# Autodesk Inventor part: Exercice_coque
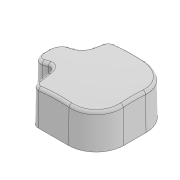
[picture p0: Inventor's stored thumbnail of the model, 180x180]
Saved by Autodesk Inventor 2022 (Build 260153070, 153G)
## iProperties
Created: 2019-12
Part Number: Exercice_coque
Material: Générique
Document SubType Name: Modeling
Designer: Fabian
Density: 1 g/cm^3
Appearance: Par défaut
Author: Fabian
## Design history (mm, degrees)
sketch "Esquisse1"
  geometry: L1 (0, 70)-(0, -66.117); L2 (90, 0)-(-70, 0); L3 (90, 14.325)-(90, 0); L4 (-70, 45)-(-70, 0); L5 (44.578, 70)-(-45, 70); L6 (86.745, 24.649)-(60.961, 61.472); L7 (83, 0)-(83, 5); L8 (65, 23)-(55, 23); L9 (43, 35)-(43, 51); L10 (31, 63)-(-18, 63); L11 (-63, 18)-(-63, 0); L12 (-63, -18)-(-63, 0); L13 (0, -70)-(0, 66.117); L14 (-70, -45)-(-70, 0); L15 (31, -63)-(-18, -63); L16 (44.578, -70)-(-45, -70); L17 (43, -35)-(43, -51); L18 (90, -14.325)-(90, 0); L19 (86.745, -24.649)-(60.961, -61.472); L20 (83, 0)-(83, -5); L21 (65, -23)-(55, -23); C1 r 4 at (-60, 60); C2 r 6 at (55, 35); C3 r 4 at (-60, -60); C4 r 6 at (55, -35); A1 r 15 centre (-60, 60) between (-51, 72) and (-72, 51); A2 r 12 centre (55, 35) between (43, 35) and (55, 23); A3 r 12 centre (31, 51) between (43, 51) and (31, 63); A4 r 18 centre (72, 14.325) between (90, 14.325) and (86.745, 24.649); A5 r 20 centre (44.578, 50) between (60.961, 61.472) and (44.578, 70); A6 r 10 centre (-45, 80) between (-51, 72) and (-45, 70); A7 r 10 centre (-80, 45) between (-70, 45) and (-72, 51); A8 r 18 centre (65, 5) between (83, 5) and (65, 23); A9 r 45 centre (-18, 18) between (-18, 63) and (-63, 18); A10 r 45 centre (-18, -18) between (-63, -18) and (-18, -63); A11 r 12 centre (31, -51) between (31, -63) and (43, -51); A12 r 10 centre (-45, -80) between (-45, -70) and (-51, -72); A13 r 15 centre (-60, -60) between (-72, -51) and (-51, -72); A14 r 10 centre (-80, -45) between (-72, -51) and (-70, -45); A15 r 12 centre (55, -35) between (55, -23) and (43, -35); A16 r 20 centre (44.578, -50) between (44.578, -70) and (60.961, -61.472); A17 r 18 centre (65, -5) between (65, -23) and (83, -5); A18 r 18 centre (72, -14.325) between (86.745, -24.649) and (90, -14.325); 7 further points
  constraints: 44 end point, 40 point on circle, 32 symmetric about line, 22 centre point, 16 tangent, 14 point on line, 5 perpendicular, 4 coincident, 3 vertical, 2 horizontal, 11 other
  dimensions: "d2" = 70 distance between parallel lines of L4 L1; "d3" = 90 distance between parallel lines of L3 L1; "d5" = 30 diameter of A1; "d6" = 140 diameter of L5 L2; "d7" = 20 distance of point (90, 20) L2.start; "d8" = 35 deg angle of L3 L6; "d9" = 120 diameter of A1.centre L2; "d11" = 60 distance from line of A1.centre L1; "d12" = 8 diameter of C1; "d13" = 70 diameter of C2.centre L2; "d14" = 55 distance from line of C2.centre L1; "d15" = 12 diameter of C2; "d16" = 83 distance between parallel lines of L7 L1; "d17" = 63 distance between parallel lines of L11 L1; "d18" = 46 diameter of L8 L2 (derived); "d19" = 126 diameter of L10 L2; "d21" = 12 radius of A2; "d22" = 43 distance between parallel lines of L9 L1 (derived); "d23" = 12 radius of A3 (derived); "d24" = 18 radius of A4 (derived); "d25" = 20 radius of A5; "d26" = 10 radius of A6; "d27" = 10 radius of A7; "d28" = 18 radius of A8; "d29" = 45 radius of A9
extrude "Extrusion1" new body sketch "Esquisse1" distance "d30" = 65; taper "d31" = -1 deg
sketch "Esquisse2"
  geometry: L1 (-81.865, 65)-(61.865, 65); L2 (0, -455)-(0, 65); L3 (18, 65)-(-31, 65) reference; L4 (-55, 65)-(-65, 65) reference; A1 r 260 centre (0, -195) between (0, -455) and (0, 65); 1 further point
  constraints: 4 end point, 2 point on circle, 1 centre point, 1 collinear, 1 point on line, 1 tangent, 1 vertical, 1 vertical alignment
  dimensions: "d32" = 520 diameter of A1
revolve "Révolution1" sketch "Esquisse2" stored, may be unused: angle "d33" = 90 deg
fillet "Congé1" dims "d36" = 5
node "Solide1"
